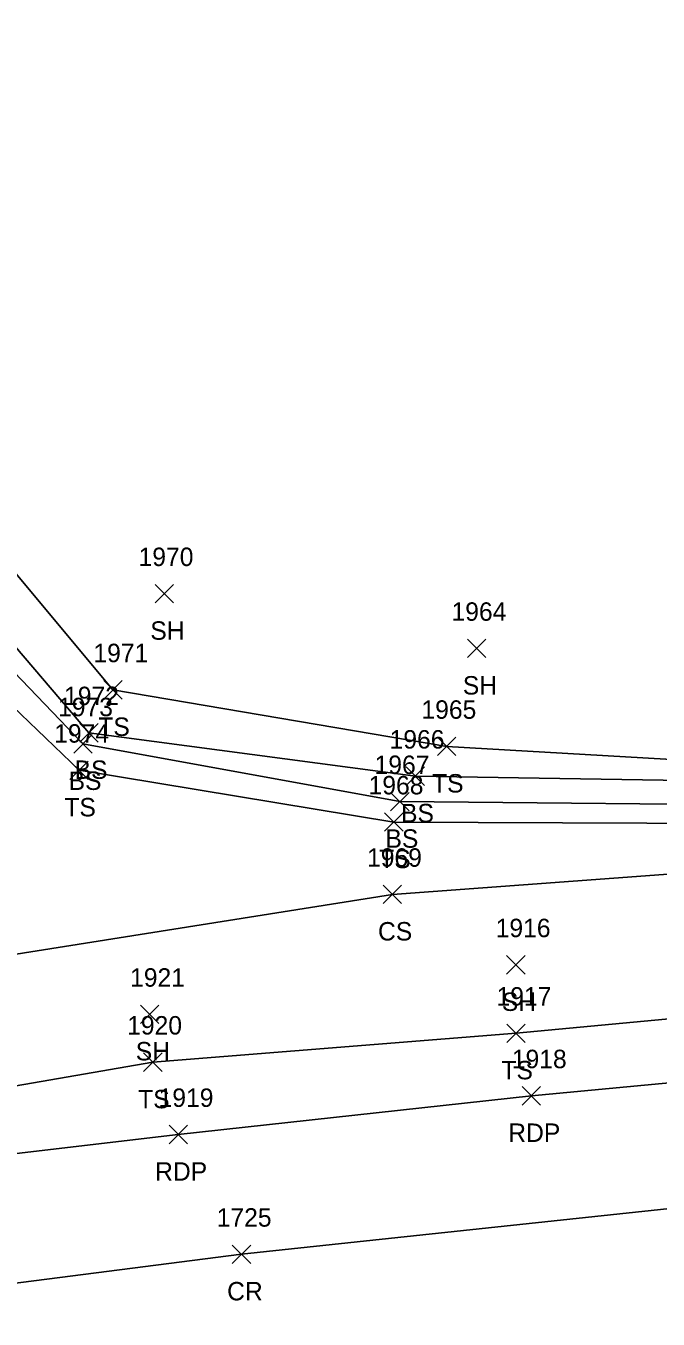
# Model space of a CAD drawing. Extents: x 1600395 to 1603269, y 874955 to 877143.
# Drawn here: x 1602002 to 1602070.6, y 875263.7 to 875404 of the extents above; entities that cross this region are included whole.
import ezdxf

# ---------------------------------------------------------------- set-up
doc = ezdxf.new("R2010")
doc.units = 0
for name, color, linetype in [('L_A', 7, 'Continuous'), ('L_I', 7, 'Continuous'), ('L_TIC', 7, 'Continuous'), ('LELB', 7, 'Continuous'), ('P_A', 7, 'Continuous'), ('P_I', 7, 'Continuous'), ('P_TIC', 7, 'Continuous'), ('PET', 7, 'Continuous'), ('PRC', 7, 'Continuous')]:
    doc.layers.add(name, color=color, linetype=linetype)

msp = doc.modelspace()

# ---------------------------------------------------------------- linework, layer by layer
at = {"layer": 'L_TIC'}
for points in [[(1602016.05, 875341.38), (1602018.05, 875343.38)], [(1602018.05, 875341.38), (1602016.05, 875343.38)], [(1602049.94, 875335.44), (1602051.94, 875337.44)], [(1602051.94, 875335.44), (1602049.94, 875337.44)], [(1602010.49, 875330.95), (1602012.49, 875332.95)], [(1602012.49, 875330.95), (1602010.49, 875332.95)], [(1602007.89, 875326.29), (1602009.89, 875328.29)], [(1602009.89, 875326.29), (1602007.89, 875328.29)], [(1602007.24, 875325.09), (1602009.24, 875327.09)], [(1602009.24, 875325.09), (1602007.24, 875327.09)], [(1602046.68, 875324.81), (1602048.68, 875326.81)], [(1602048.68, 875324.81), (1602046.68, 875326.81)], [(1602006.81, 875322.22), (1602008.81, 875324.22)], [(1602008.81, 875322.22), (1602006.81, 875324.22)], [(1602043.28, 875321.58), (1602045.28, 875323.58)], [(1602045.28, 875321.58), (1602043.28, 875323.58)], [(1602041.6, 875318.82), (1602043.6, 875320.82)], [(1602043.6, 875318.82), (1602041.6, 875320.82)], [(1602040.95, 875316.61), (1602042.95, 875318.61)], [(1602042.95, 875316.61), (1602040.95, 875318.61)], [(1602040.79, 875308.76), (1602042.79, 875310.76)], [(1602042.79, 875308.76), (1602040.79, 875310.76)], [(1602054.17, 875301.12), (1602056.17, 875303.12)], [(1602056.17, 875301.12), (1602054.17, 875303.12)], [(1602014.47, 875295.75), (1602016.47, 875297.75)], [(1602016.47, 875295.75), (1602014.47, 875297.75)], [(1602054.2, 875293.7), (1602056.2, 875295.7)], [(1602056.2, 875293.7), (1602054.2, 875295.7)], [(1602014.81, 875290.56), (1602016.81, 875292.56)], [(1602016.81, 875290.56), (1602014.81, 875292.56)]]:
    msp.add_lwpolyline(points, dxfattribs=at)
at = {"layer": 'LELB'}
for points in [[(1602130.78, 875324.37), (1602086.45, 875323.55), (1602047.68, 875325.81), (1602011.49, 875331.95), (1601986.1, 875362.37), (1601981.1, 875381.42), (1601928.66, 875403.97)], [(1602130.81, 875321.99), (1602086.81, 875321.91), (1602044.28, 875322.58), (1602008.89, 875327.29), (1601983.72, 875356.75), (1601975.47, 875363.36), (1601927.66, 875400.9)], [(1602174.04, 875317.39), (1602130.36, 875320.32), (1602087.23, 875319.39), (1602042.6, 875319.82), (1602008.24, 875326.09), (1601982.5, 875352.91), (1601973.75, 875359.58), (1601926.73, 875398.96)], [(1602129.74, 875318.21), (1602087.66, 875317.41), (1602041.95, 875317.61), (1602007.81, 875323.22), (1601980.7, 875349.27), (1601972.05, 875352.54), (1601923.26, 875397.15)], [(1602130.11, 875313.96), (1602085.41, 875312.98), (1602041.79, 875309.76), (1601997.3, 875302.71), (1601977.69, 875304.1), (1601966.14, 875308.98), (1601978.91, 875327.88)], [(1602400.49, 875294.37), (1602361.79, 875296.79), (1602320.07, 875299.51), (1602288.68, 875301.16), (1602257.59, 875301.18), (1602210.36, 875302.47), (1602169.51, 875304.24), (1602128.15, 875302.21), (1602094.95, 875298.42), (1602055.2, 875294.7), (1602015.81, 875291.56), (1601985.08, 875286.24), (1601964.25, 875289.69), (1601956.22, 875288.12), (1601952.74, 875279.27)]]:
    msp.add_lwpolyline(points, dxfattribs=at)
at = {"layer": 'P_TIC'}
for points in [[(1602055.86, 875286.91), (1602057.86, 875288.91)], [(1602057.86, 875286.91), (1602055.86, 875288.91)], [(1602017.57, 875282.71), (1602019.57, 875284.71)], [(1602019.57, 875282.71), (1602017.57, 875284.71)], [(1602024.43, 875269.72), (1602026.43, 875271.72)], [(1602026.43, 875269.72), (1602024.43, 875271.72)]]:
    msp.add_lwpolyline(points, dxfattribs=at)
at = {"layer": 'PET'}
msp.add_lwpolyline([(1602400.31, 875290.46), (1602361.62, 875292.91), (1602320.01, 875295.06), (1602288.5, 875296.29), (1602257.26, 875296.75), (1602210.13, 875296.36), (1602169.38, 875295.49), (1602128.8, 875293.68), (1602096.32, 875291.62), (1602056.86, 875287.91), (1602018.57, 875283.71), (1601986.25, 875279.93), (1601962.94, 875277.18), (1601953.76, 875275.85), (1601921.23, 875272), (1601886.39, 875267.75)], dxfattribs=at)
at = {"layer": 'PRC'}
msp.add_lwpolyline([(1602402.71, 875276.76), (1602360.41, 875278.94), (1602318.06, 875280.96), (1602289.17, 875282.16), (1602257.66, 875282.81), (1602210.34, 875283), (1602169.35, 875282.18), (1602129.85, 875280.43), (1602107.17, 875278.74), (1602075.28, 875276.04), (1602025.43, 875270.72), (1601983.16, 875265.3), (1601954.29, 875261.32), (1601930.37, 875258.06), (1601901.66, 875254.25), (1601879.64, 875251.36)], dxfattribs=at)

# ---------------------------------------------------------------- texts
at = {"layer": 'L_A'}
for s, p in [('SH', (1602015.54, 875337.38)), ('SH', (1602049.43, 875331.44)), ('TS', (1602009.9, 875326.95)), ('BS', (1602007.33, 875322.29)), ('BS', (1602006.68, 875321.09)), ('TS', (1602046.09, 875320.81)), ('TS', (1602006.22, 875318.22)), ('BS', (1602042.73, 875317.58)), ('BS', (1602041.04, 875314.82)), ('TS', (1602040.36, 875312.61)), ('CS', (1602040.23, 875304.76)), ('SH', (1602053.66, 875297.12)), ('SH', (1602013.96, 875291.75)), ('TS', (1602053.61, 875289.7)), ('TS', (1602014.22, 875286.56))]:
    msp.add_text(s, height=2, dxfattribs=at).set_placement(p)
at = {"layer": 'L_I'}
for s, p in [('1970', (1602014.27, 875345.38)), ('1964', (1602048.2, 875339.44)), ('1971', (1602009.37, 875334.95)), ('1972', (1602006.19, 875330.29)), ('1973', (1602005.54, 875329.09)), ('1965', (1602044.94, 875328.81)), ('1974', (1602005.12, 875326.22)), ('1966', (1602041.49, 875325.58)), ('1967', (1602039.86, 875322.82)), ('1968', (1602039.21, 875320.61)), ('1969', (1602039.04, 875312.76)), ('1916', (1602052.99, 875305.12)), ('1921', (1602013.35, 875299.75)), ('1917', (1602053.08, 875297.7)), ('1920', (1602013.03, 875294.56))]:
    msp.add_text(s, height=2, dxfattribs=at).set_placement(p)
at = {"layer": 'P_A'}
for s, p in [('RDP', (1602054.35, 875282.91)), ('RDP', (1602016.06, 875278.71)), ('CR', (1602023.87, 875265.72))]:
    msp.add_text(s, height=2, dxfattribs=at).set_placement(p)
at = {"layer": 'P_I'}
for s, p in [('1918', (1602054.74, 875290.91)), ('1919', (1602016.44, 875286.71)), ('1725', (1602022.74, 875273.72))]:
    msp.add_text(s, height=2, dxfattribs=at).set_placement(p)

doc.saveas('drawing.dxf')
